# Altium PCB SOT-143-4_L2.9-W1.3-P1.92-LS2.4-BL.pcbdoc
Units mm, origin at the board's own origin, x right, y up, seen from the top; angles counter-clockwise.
Board outline 16.13 x 15.92 mm, 2 copper layers (Top Layer, Bottom Layer), stack 0 mm thick; 1 components, 0 nets, 4 pads, 0 vias.
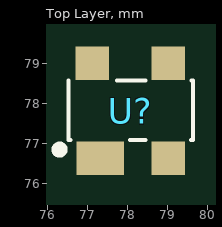
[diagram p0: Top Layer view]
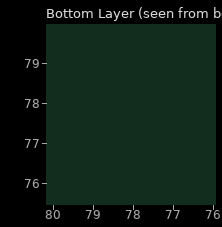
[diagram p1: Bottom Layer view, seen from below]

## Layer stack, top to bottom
Top Layer: signal copper (thickness not stored)
Bottom Layer: signal copper (thickness not stored)

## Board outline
85.98,69.85 69.85,69.85 69.85,85.771 85.98,85.771

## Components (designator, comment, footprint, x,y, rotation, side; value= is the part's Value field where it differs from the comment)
U? "" SOT-143-4_L2.9-W1.3-P1.92-LS2.4-BL 78.07,77.81 r0 top

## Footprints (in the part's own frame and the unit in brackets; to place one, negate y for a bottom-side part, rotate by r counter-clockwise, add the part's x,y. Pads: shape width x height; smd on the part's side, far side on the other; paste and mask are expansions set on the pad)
SOT-143-4_L2.9-W1.3-P1.92-LS2.4-BL [mil]
  rect 47x33 smd: 1(-29.53,-46.91)
  rect 33x33 smd: 2(37.4,-46.91) 3(37.4,46.9) 4(-37.4,46.9)
  silkscreen extent -74,-42 61,30

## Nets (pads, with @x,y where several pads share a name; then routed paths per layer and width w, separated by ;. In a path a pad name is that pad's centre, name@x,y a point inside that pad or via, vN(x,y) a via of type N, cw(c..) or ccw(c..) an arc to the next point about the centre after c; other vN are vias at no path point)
pads on no net: U?.1 U?.2 U?.3 U?.4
